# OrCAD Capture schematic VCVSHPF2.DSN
size A
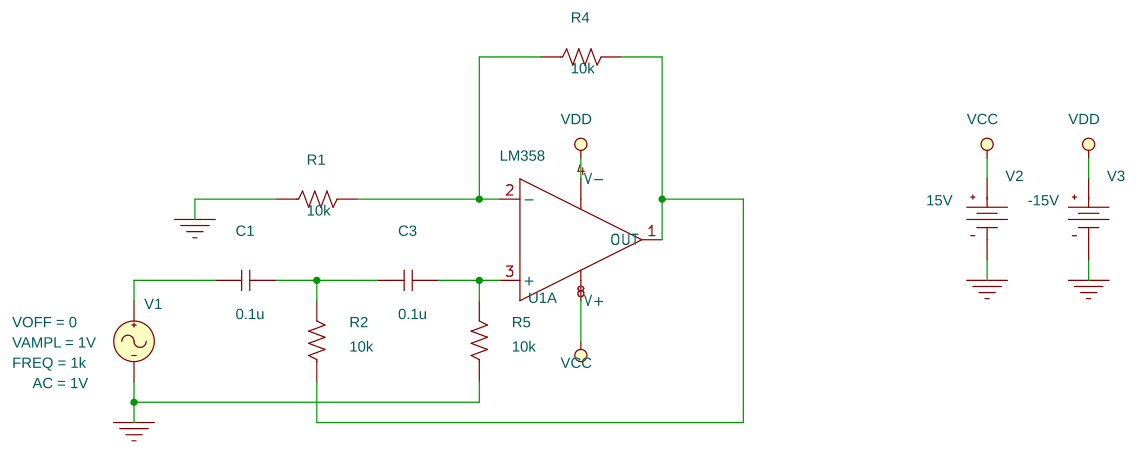
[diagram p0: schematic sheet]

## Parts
C1  0.1u  [cap196]
C3  0.1u  [cap196]
R1  10k  [AXRC05]
R2  10k  [AXRC05]
R4  10k  [AXRC05]
R5  10k  [AXRC05]
U1  LM358  [DIP1008W300L450]  (section A)
V1  VSIN
V2  VDC
V3  VDC

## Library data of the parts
C1 C3 = C
R1 R2 R4 R5 = R
U1 = LM358
V1 = VSIN: AC: 1V; FREQ: 1k; VAMPL: 1V; VOFF: 0
V2 = VDC: DC: 15V
V3 = VDC: DC: -15V

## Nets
VCC: U1.8(V+) V2.0(+)
VDD: U1.4(V-) V3.0(+)
0: R1.1 R5.1 V1.2(-) V2.1(-) V3.1(-)
N01802: R1.2 R4.1 U1.2(-)
N01812: R2.1 R4.2 U1.1(OUT)
N02048: C1.2 V1.1(+)
N02058: C1.1 C3.2 R2.2
N02072: C3.1 R5.2 U1.3(+)
